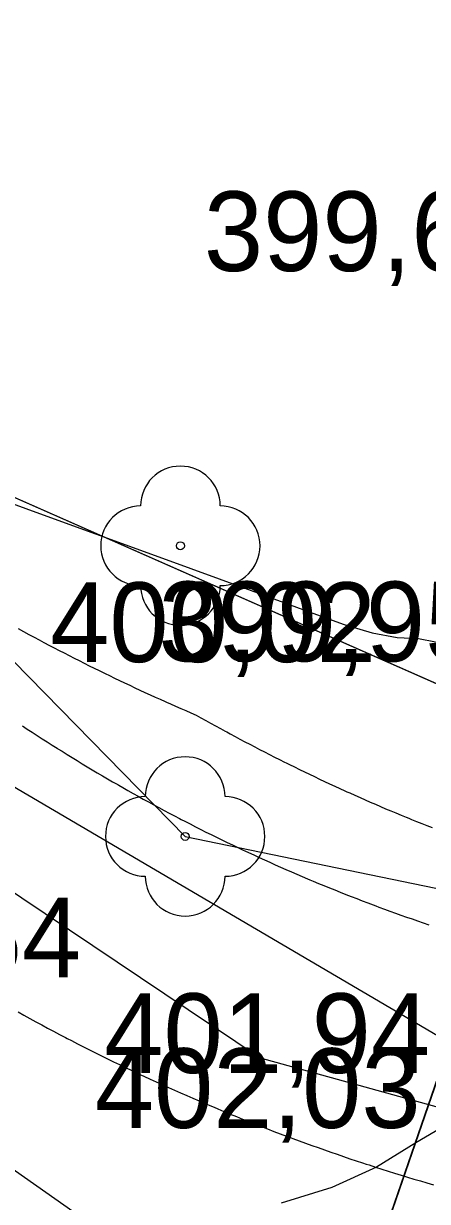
# Model space of a CAD drawing. Extents: x -574342 to -508101, y -1143544 to -1123894.
# Drawn here: x -508401.18 to -508396.11, y -1143322.98 to -1143308.19 of the extents above; entities that cross this region are included whole.
import ezdxf

# ---------------------------------------------------------------- set-up
doc = ezdxf.new("R2010")
doc.units = 0
for name, color, linetype in [('01_PARCELY_NAVRH_PC', 7, 'Continuous'), ('01_PARCELY_NAVRH_ŽP', 7, 'Continuous'), ('1000', 7, 'Continuous'), ('21', 7, 'Continuous'), ('37', 7, 'Continuous'), ('54', 7, 'Continuous'), ('55', 7, 'Continuous'), ('60', 7, 'Continuous'), ('Level 255', 7, 'Continuous'), ('VRST HL', 7, 'Continuous'), ('VRST VEDL', 7, 'Continuous')]:
    doc.layers.add(name, color=color, linetype=linetype)

msp = doc.modelspace()

# ---------------------------------------------------------------- linework, layer by layer
at = {"layer": '01_PARCELY_NAVRH_PC'}
msp.add_lwpolyline([(-508451.57, -1143168.14), (-508437.66, -1143207.58), (-508425.52, -1143241.92), (-508422.7, -1143249.88), (-508420.08, -1143265.35), (-508416.18, -1143288.91), (-508414.34, -1143296.2), (-508410.3, -1143304.94), (-508406.96, -1143310.33), (-508402.64, -1143313.55), (-508394.5, -1143317.14), (-508397.53, -1143325.93), (-508402.47, -1143323.55), (-508407.39, -1143320.93), (-508414.82, -1143312.69), (-508418.17, -1143303.49), (-508422.28, -1143289.33), (-508426.41, -1143265.09), (-508431, -1143245.85), (-508431.86, -1143242.81), (-508432.73, -1143240.34), (-508445.99, -1143206.42), (-508454.33, -1143183.49)], dxfattribs=at)
msp.add_lwpolyline([(-508397.53, -1143325.93), (-508394.5, -1143317.14), (-508377.05, -1143323.29), (-508363.05, -1143330.55), (-508352.96, -1143343.32), (-508344.87, -1143376.79), (-508339.52, -1143391.27), (-508327.86, -1143416.88), (-508328.32, -1143431.04), (-508330.46, -1143435.46), (-508335.26, -1143435.36), (-508332.66, -1143429.91), (-508332.21, -1143424.5), (-508336.31, -1143410.38), (-508344.81, -1143391.35), (-508348.55, -1143381.54), (-508357.56, -1143346.15), (-508363.15, -1143337.53), (-508370.86, -1143331.67), (-508380.92, -1143326.77), (-508388.37, -1143325.84)], close=True, dxfattribs=at)
at = {"layer": '01_PARCELY_NAVRH_ŽP'}
msp.add_lwpolyline([(-508355.53, -1143335.68), (-508361.58, -1143328.14), (-508368.91, -1143322.84), (-508376.72, -1143318.72), (-508388.31, -1143315.9), (-508393.87, -1143311.09), (-508396.73, -1143306.67), (-508414.23, -1143256.72), (-508419.24, -1143259.91), (-508420.08, -1143265.35), (-508416.18, -1143288.91), (-508414.34, -1143296.2), (-508410.3, -1143304.94), (-508406.96, -1143310.33), (-508402.64, -1143313.55), (-508394.5, -1143317.14), (-508377.05, -1143323.29), (-508363.05, -1143330.55), (-508352.96, -1143343.32)], dxfattribs=at)
at = {"layer": '1000'}
for points in [[(-508401.245, -1143315.79), (-508401.11, -1143315.864), (-508401.047, -1143315.898), (-508400.984, -1143315.931), (-508400.922, -1143315.964), (-508400.917, -1143315.967), (-508400.859, -1143315.998), (-508400.796, -1143316.03), (-508400.733, -1143316.063), (-508400.67, -1143316.096), (-508400.607, -1143316.128), (-508400.544, -1143316.16), (-508400.481, -1143316.192), (-508400.418, -1143316.224), (-508400.355, -1143316.256), (-508400.291, -1143316.287), (-508400.228, -1143316.318), (-508400.164, -1143316.349), (-508400.155, -1143316.354), (-508400.101, -1143316.38), (-508400.037, -1143316.411), (-508399.974, -1143316.441), (-508399.91, -1143316.472), (-508399.846, -1143316.502), (-508399.783, -1143316.532), (-508399.719, -1143316.561), (-508399.655, -1143316.591), (-508399.591, -1143316.62), (-508399.527, -1143316.649), (-508399.463, -1143316.678), (-508399.399, -1143316.707), (-508399.385, -1143316.713), (-508399.335, -1143316.736), (-508399.27, -1143316.764), (-508399.206, -1143316.792), (-508399.142, -1143316.82), (-508399.077, -1143316.848), (-508399.013, -1143316.876), (-508398.952, -1143316.909), (-508398.891, -1143316.943), (-508398.83, -1143316.977), (-508398.769, -1143317.011), (-508398.708, -1143317.045), (-508398.647, -1143317.078), (-508398.629, -1143317.088), (-508398.585, -1143317.111), (-508398.524, -1143317.145), (-508398.462, -1143317.178), (-508398.401, -1143317.21), (-508398.339, -1143317.243), (-508398.277, -1143317.275), (-508398.215, -1143317.307), (-508398.153, -1143317.339), (-508398.091, -1143317.371), (-508398.028, -1143317.403), (-508397.966, -1143317.434), (-508397.904, -1143317.465), (-508397.882, -1143317.476), (-508397.841, -1143317.497), (-508397.778, -1143317.527), (-508397.716, -1143317.558), (-508397.653, -1143317.589), (-508397.59, -1143317.619), (-508397.527, -1143317.649), (-508397.464, -1143317.679), (-508397.4, -1143317.709), (-508397.337, -1143317.738), (-508397.273, -1143317.768), (-508397.21, -1143317.797), (-508397.146, -1143317.826), (-508397.12, -1143317.838), (-508397.083, -1143317.854), (-508397.019, -1143317.883), (-508396.955, -1143317.911), (-508396.891, -1143317.94), (-508396.827, -1143317.968), (-508396.762, -1143317.995), (-508396.698, -1143318.023), (-508396.634, -1143318.051), (-508396.569, -1143318.078), (-508396.505, -1143318.105), (-508396.44, -1143318.132), (-508396.375, -1143318.158), (-508396.344, -1143318.171), (-508396.31, -1143318.185), (-508396.246, -1143318.211), (-508396.181, -1143318.237), (-508396.115, -1143318.263), (-508396.05, -1143318.288)], [(-508401.192, -1143317.011), (-508401.131, -1143317.052), (-508401.069, -1143317.092), (-508401.007, -1143317.133), (-508400.945, -1143317.173), (-508400.883, -1143317.213), (-508400.82, -1143317.253), (-508400.758, -1143317.292), (-508400.748, -1143317.298), (-508400.695, -1143317.331), (-508400.632, -1143317.37), (-508400.569, -1143317.409), (-508400.506, -1143317.448), (-508400.443, -1143317.486), (-508400.38, -1143317.525), (-508400.316, -1143317.563), (-508400.253, -1143317.6), (-508400.189, -1143317.638), (-508400.125, -1143317.675), (-508400.061, -1143317.712), (-508399.997, -1143317.749), (-508399.983, -1143317.757), (-508399.933, -1143317.786), (-508399.869, -1143317.823), (-508399.804, -1143317.859), (-508399.74, -1143317.895), (-508399.675, -1143317.931), (-508399.61, -1143317.966), (-508399.545, -1143318.002), (-508399.48, -1143318.037), (-508399.415, -1143318.072), (-508399.35, -1143318.107), (-508399.284, -1143318.141), (-508399.219, -1143318.176), (-508399.2, -1143318.185), (-508399.153, -1143318.21), (-508399.087, -1143318.243), (-508399.021, -1143318.277), (-508398.955, -1143318.311), (-508398.889, -1143318.344), (-508398.823, -1143318.377), (-508398.757, -1143318.409), (-508398.69, -1143318.442), (-508398.624, -1143318.474), (-508398.557, -1143318.506), (-508398.49, -1143318.538), (-508398.424, -1143318.57), (-508398.4, -1143318.581), (-508398.357, -1143318.601), (-508398.29, -1143318.632), (-508398.222, -1143318.663), (-508398.155, -1143318.694), (-508398.088, -1143318.724), (-508398.02, -1143318.755), (-508397.953, -1143318.785), (-508397.885, -1143318.815), (-508397.817, -1143318.844), (-508397.749, -1143318.873), (-508397.681, -1143318.903), (-508397.613, -1143318.931), (-508397.585, -1143318.944), (-508397.545, -1143318.96), (-508397.477, -1143318.989), (-508397.408, -1143319.017), (-508397.34, -1143319.045), (-508397.271, -1143319.072), (-508397.203, -1143319.1), (-508397.134, -1143319.127), (-508397.065, -1143319.154), (-508396.996, -1143319.181), (-508396.927, -1143319.208), (-508396.858, -1143319.234), (-508396.789, -1143319.26), (-508396.755, -1143319.273), (-508396.72, -1143319.286), (-508396.65, -1143319.312), (-508396.581, -1143319.337), (-508396.511, -1143319.362), (-508396.442, -1143319.387), (-508396.372, -1143319.412), (-508396.302, -1143319.436), (-508396.232, -1143319.46), (-508396.162, -1143319.484), (-508396.092, -1143319.508)]]:
    msp.add_lwpolyline(points, dxfattribs=at)
at = {"layer": '21'}
msp.add_lwpolyline([(-508401.246, -1143320.604), (-508401.173, -1143320.645), (-508401.099, -1143320.686), (-508401.024, -1143320.726), (-508400.95, -1143320.766), (-508400.876, -1143320.806), (-508400.801, -1143320.846), (-508400.727, -1143320.885), (-508400.652, -1143320.924), (-508400.631, -1143320.935), (-508400.577, -1143320.963), (-508400.502, -1143321.002), (-508400.427, -1143321.04), (-508400.351, -1143321.078), (-508400.276, -1143321.116), (-508400.2, -1143321.154), (-508400.125, -1143321.191), (-508400.049, -1143321.228), (-508399.973, -1143321.265), (-508399.897, -1143321.302), (-508399.821, -1143321.338), (-508399.744, -1143321.374), (-508399.717, -1143321.387), (-508399.668, -1143321.41), (-508399.591, -1143321.446), (-508399.515, -1143321.481), (-508399.438, -1143321.516), (-508399.361, -1143321.551), (-508399.284, -1143321.586), (-508399.207, -1143321.62), (-508399.129, -1143321.654), (-508399.052, -1143321.688), (-508398.974, -1143321.721), (-508398.897, -1143321.754), (-508398.819, -1143321.787), (-508398.787, -1143321.801), (-508398.741, -1143321.82), (-508398.663, -1143321.852), (-508398.585, -1143321.885), (-508398.507, -1143321.917), (-508398.429, -1143321.948), (-508398.35, -1143321.98), (-508398.272, -1143322.011), (-508398.193, -1143322.042), (-508398.115, -1143322.072), (-508398.036, -1143322.103), (-508397.957, -1143322.133), (-508397.878, -1143322.162), (-508397.84, -1143322.177), (-508397.799, -1143322.192), (-508397.72, -1143322.221), (-508397.64, -1143322.25), (-508397.561, -1143322.279), (-508397.482, -1143322.307), (-508397.402, -1143322.336), (-508397.322, -1143322.364), (-508397.243, -1143322.391), (-508397.163, -1143322.419), (-508397.083, -1143322.446), (-508397.003, -1143322.473), (-508396.923, -1143322.499), (-508396.878, -1143322.514), (-508396.842, -1143322.525), (-508396.762, -1143322.551), (-508396.682, -1143322.577), (-508396.601, -1143322.603), (-508396.521, -1143322.628), (-508396.44, -1143322.653), (-508396.359, -1143322.678), (-508396.278, -1143322.702), (-508396.197, -1143322.726), (-508396.116, -1143322.75), (-508396.035, -1143322.773)], dxfattribs=at)
at = {"layer": '37'}
msp.add_lwpolyline([(-508408.82, -1143311.83), (-508404.37, -1143317.04), (-508398.21, -1143321.18), (-508393.66, -1143322.44), (-508393.79, -1143324.58), (-508400.56, -1143323.11), (-508406.32, -1143319.06), (-508411.41, -1143313.16), (-508415.31, -1143305.9), (-508419.33, -1143292.88), (-508424.96, -1143264.72), (-508428.49, -1143248.11), (-508430.27, -1143242.09), (-508442.28, -1143211.48), (-508455.59, -1143171.17), (-508460.82, -1143160.05), (-508470.5, -1143142.85)], dxfattribs=at)
msp.add_lwpolyline([(-508408.82, -1143311.83), (-508404.37, -1143317.04), (-508398.21, -1143321.18), (-508393.66, -1143322.44), (-508393.79, -1143324.58), (-508400.56, -1143323.11), (-508406.32, -1143319.06), (-508411.41, -1143313.16), (-508415.31, -1143305.9), (-508419.33, -1143292.88), (-508424.96, -1143264.72), (-508428.49, -1143248.11), (-508430.27, -1143242.09), (-508442.28, -1143211.48), (-508455.59, -1143171.17), (-508460.82, -1143160.05), (-508470.5, -1143142.85)], dxfattribs=at)
at = {"layer": '54'}
for centre in [(-508399.21, -1143314.75), (-508399.15, -1143318.4)]:
    msp.add_circle(centre, 0.05, dxfattribs=at)
for centre, start, end in [((-508399.21, -1143314.25), 0, 180), ((-508399.71, -1143314.75), 90, 270), ((-508398.71, -1143314.75), 270, 90), ((-508399.21, -1143315.25), 180, 0), ((-508399.15, -1143317.9), 0, 180), ((-508399.65, -1143318.4), 90, 270), ((-508398.65, -1143318.4), 270, 90), ((-508399.15, -1143318.9), 180, 0)]:
    msp.add_arc(centre, 0.5, start, end, dxfattribs=at)
at = {"layer": '55'}
for points in [[(-508399.15, -1143318.4), (-508408.17, -1143309.19), (-508414.22, -1143295.92)], [(-508399.15, -1143318.4), (-508408.17, -1143309.19), (-508414.22, -1143295.92)], [(-508399.15, -1143318.4), (-508387.42, -1143320.82), (-508372.09, -1143324.77), (-508360.95, -1143333.07), (-508355.89, -1143338.48), (-508352.03, -1143348.55), (-508344.68, -1143378.31)], [(-508399.15, -1143318.4), (-508387.42, -1143320.82), (-508372.09, -1143324.77), (-508360.95, -1143333.07), (-508355.89, -1143338.48), (-508352.03, -1143348.55), (-508344.68, -1143378.31)]]:
    msp.add_lwpolyline(points, dxfattribs=at)
at = {"layer": '60'}
for points in [[(-508409.76, -1143308.26), (-508402.64, -1143313.55), (-508394.5, -1143317.14), (-508378.66, -1143319), (-508370.76, -1143321.98), (-508364.58, -1143327.7), (-508357.83, -1143334.71), (-508355.73, -1143339.75)], [(-508355.73, -1143339.75), (-508359.33, -1143335.96), (-508366.15, -1143330.14), (-508372.96, -1143325.89), (-508380.12, -1143322.64), (-508395.65, -1143321.1), (-508404.67, -1143315.8), (-508409.76, -1143308.26)], [(-508409.76, -1143308.26), (-508402.64, -1143313.55), (-508394.5, -1143317.14), (-508378.66, -1143319), (-508370.76, -1143321.98), (-508364.58, -1143327.7), (-508357.83, -1143334.71), (-508355.73, -1143339.75)], [(-508355.73, -1143339.75), (-508359.33, -1143335.96), (-508366.15, -1143330.14), (-508372.96, -1143325.89), (-508380.12, -1143322.64), (-508395.65, -1143321.1), (-508404.67, -1143315.8), (-508409.76, -1143308.26)]]:
    msp.add_lwpolyline(points, dxfattribs=at)
at = {"layer": 'VRST HL'}
msp.add_lwpolyline([(-508402.067, -1143313.947), (-508401.024, -1143314.328), (-508399.482, -1143314.889), (-508398.323, -1143315.311), (-508397.547, -1143315.595), (-508397.153, -1143315.74), (-508396.801, -1143315.842), (-508396.49, -1143315.9), (-508396.22, -1143315.915), (-508396.009, -1143315.955)], dxfattribs=at)
at = {"layer": 'VRST VEDL'}
msp.add_lwpolyline([(-508395.892, -1143322.033), (-508396.254, -1143322.249), (-508396.747, -1143322.554), (-508397.311, -1143322.806), (-508397.946, -1143323.006)], dxfattribs=at)

# ---------------------------------------------------------------- texts
at = {"layer": 'Level 255'}
for s, p in [('399,67', (-508398.915, -1143311.3)), ('400,02', (-508400.845, -1143316.21)), ('399,95', (-508399.485, -1143316.2)), ('401,54', (-508404.545, -1143320.17)), ('401,94', (-508400.165, -1143321.37)), ('402,03', (-508400.285, -1143322.06))]:
    msp.add_text(s, height=1, dxfattribs=at).set_placement(p)

doc.saveas('drawing.dxf')
